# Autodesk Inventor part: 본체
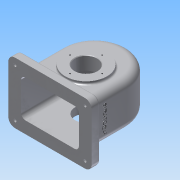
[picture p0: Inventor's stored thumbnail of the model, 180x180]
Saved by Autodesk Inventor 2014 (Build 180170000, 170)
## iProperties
Created: 2016-10
Part Number: 본체
Material: 알루미늄 6061
Document SubType Name: Modeling
Designer: net
Density: 2.71 g/cm^3
Appearance: 알루미늄 - 평지
Author: net
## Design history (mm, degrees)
sketch "스케치1"
  geometry: L1 (-63, 55)-(63, 55); L2 (75, 43)-(75, -43); L3 (63, -55)-(-63, -55); L4 (-75, -43)-(-75, 43); L5 (-75, 55)-(75, -55); L6 (75, 55)-(-75, -55); A1 r 12 centre (63, -43) between (63, -55) and (75, -43); A2 r 12 centre (-63, -43) between (-75, -43) and (-63, -55); A3 r 12 centre (-63, 43) between (-63, 55) and (-75, 43); A4 r 12 centre (63, 43) between (75, 43) and (63, 55); 1 further point
  constraints: 12 end point, 8 point on circle, 8 point on line, 8 tangent, 4 centre point, 3 equal radius, 2 midpoint, 2 parallel, 1 horizontal, 1 perpendicular
  dimensions: "d0" = 150 distance of L5.end L6.end; "d1" = 110 distance of L6.start L5.end; "d2" = 12 radius of A1
extrude "돌출1" new body sketch "스케치1" distance "d3" = 15; taper "d4" = 0 deg
fillet "모깎기1" dims "d5" = 3
sketch "스케치2"
  geometry: L1 (-58, 0)-(58, 0); L2 (58, 0)-(58, 80); L3 (58, 80)-(-58, 80); L4 (-58, 80)-(-58, 0); 2 further points
  constraints: 8 end point, 2 coincident, 2 parallel, 1 horizontal, 1 midpoint, 1 perpendicular
  dimensions: "d6" = 116 distance of L3.end L2.end; "d7" = 80 distance of L2.end L1.end
extrude "돌출2" join sketch "스케치2" stored distance "d8" = 77; taper "d9" = 0 deg
sketch "스케치3"
  geometry: L1 (-58, 80)-(58, 80) reference; 2 further points
  constraints: 1 horizontal alignment, 1 midpoint, 2 other
extrude "돌출3" join sketch "스케치3" stored distance "d10" = 77; taper "d11" = 0 deg
sketch "스케치4"
  geometry: L1 (-58, 15)-(-58, 80) reference; L2 (58, 80)-(58, 15) reference; L3 (-63, 0)-(63, 0) reference; L4 (-52, 0)-(-52, 80); L5 (52, 80)-(52, 0); L6 (52, 0)-(-52, 0); A1 r 58 centre (0, 80) between (58, 80) and (-58, 80) reference; A2 r 52 centre (0, 80) between (52, 80) and (-52, 80); 1 further point
  constraints: 6 end point, 2 parallel, 2 point on circle, 2 point on line, 2 tangent, 1 centre point, 1 collinear
  dimensions: "d12" = 6 radial gap between concentric circles of A2 A1
extrude "돌출4" cut sketch "스케치4" stored distance "d13" = 67; taper "d14" = 0 deg
sketch "스케치5"
  geometry: L1 (63, 0)-(-63, 0) reference; C1 r 31 at (0, 65); 2 further points
  constraints: 1 centre point, 1 midpoint, 1 vertical alignment
  dimensions: "d15" = 62 diameter of C1; "d16" = 65 distance from line of L1 C1.centre
extrude "돌출5" join sketch "스케치5" distance "d17" = 10; taper "d18" = 0 deg
sketch "스케치6"
  geometry: C1 r 31 at (0, 0) reference; C2 r 20 at (0, 0); 1 further point
  constraints: 1 centre point, 1 coincident
  dimensions: "d19" = 40 diameter of C2
extrude "돌출6" cut sketch "스케치6" distance "d20" = 15; taper "d21" = 0 deg
sketch "스케치7"
  geometry: L1 (63, 0)-(-63, 0) reference; C1 r 37.5 at (0, 65); 2 further points
  constraints: 1 centre point, 1 midpoint, 1 vertical alignment
  dimensions: "d22" = 75 diameter of C1; "d23" = 65 distance from line of L1 C1.centre
extrude "돌출7" join sketch "스케치7" distance "d24" = 5; taper "d25" = 0 deg
sketch "스케치8"
  geometry: C1 r 37.5 at (0, 0) reference; C2 r 20 at (0, 0); 1 further point
  constraints: 1 centre point, 1 coincident
  dimensions: "d26" = 40 diameter of C2
extrude "돌출8" cut sketch "스케치8" distance "d27" = 24; taper "d28" = 0 deg
sketch "스케치9"
  geometry: C1 r 20 at (0, 65) reference; C2 r 28 at (0, 65); 1 further point
  constraints: 1 centre point, 1 coincident
  dimensions: "d29" = 56 diameter of C2
extrude "돌출9" join sketch "스케치9" distance "d30" = 14; taper "d31" = 0 deg
feature "면 기울기1" dims angle "d32" = 40 deg
sketch "스케치11"
  geometry: A1 r 9 centre (63, 43) between (72, 43) and (63, 52) reference; A2 r 9 centre (-63, 43) between (-63, 52) and (-72, 43) reference; A3 r 9 centre (-63, -43) between (-72, -43) and (-63, -52) reference; A4 r 9 centre (63, -43) between (63, -52) and (72, -43) reference; 5 further points
  constraints: 4 coincident
hole "구멍1" sketch "스케치11" at (-63, 43), (63, 43), (63, -43), (-63, -43) diameter "d33" = 5; stored, may be unused: countersink angle "d37" = 90 deg, drill point angle "d39" = 0 deg; dims "d34" = 6, "d35" = 12, "d36" = 5, "d38" = 20
fillet "모깎기2" dims "d40" = 13, "d41" = 8
node "작업 평면1"
sketch "스케치12"
  geometry: C1 r 6 at (0, 0); 1 further point
  constraints: 1 centre point, 1 coincident
  dimensions: "d43" = 12 diameter of C1
extrude "돌출10" join sketch "스케치12" stored distance "d44" = 14; taper "d45" = 0 deg
feature "면 기울기2" dims angle "d46" = 10 deg
sketch "스케치14"
  geometry: C1 r 6 at (0, 0) reference; 1 further point
  constraints: 1 coincident
hole "구멍2" sketch "스케치14" at (0, 0) diameter "d47" = 4.459; stored, may be unused: countersink angle "d51" = 90 deg, drill point angle "d53" = 118 deg; dims "d48" = 30, "d49" = 12, "d50" = 5, "d52" = 30
sketch "스케치15"
  geometry: C1 r 20 at (0, 0) reference; 5 further points
  constraints: 1 horizontal alignment, 5 other
  dimensions: "d54" = 29 distance of point (29, 0) C1.centre; "d57" = 360 deg dimension on C1.centre point (29, 0) (derived)
hole "구멍3" sketch "스케치15" at (29, 0), (0, 29), (-29, 0), (0, -29) diameter "d59" = 2.459; stored, may be unused: countersink angle "d63" = 90 deg, drill point angle "d65" = 118 deg; dims "d60" = 6, "d61" = 4, "d62" = 2, "d64" = 8
sketch "스케치16"
  geometry: C1 r 20 at (0, 0) reference; 5 further points
  constraints: 1 horizontal alignment, 5 other
  dimensions: "d66" = 26 distance of point (26, 0) C1.centre; "d69" = 360 deg dimension on C1.centre point (26, 0) (derived)
hole "구멍4" sketch "스케치16" at (26, 0), (0, 26), (-26, 0), (0, -26) diameter "d71" = 2.459; stored, may be unused: countersink angle "d75" = 90 deg, drill point angle "d77" = 118 deg; dims "d72" = 6, "d73" = 4, "d74" = 2, "d76" = 8
chamfer "모따기1" distance "d78" = 1; stored, may be unused: second distance "d79" = 2, angle "d80" = 45 deg
node "작업 평면2"
sketch "스케치17"
  geometry: L1 (17.5, -15)-(-68.5, -15) reference; 3 further points
  constraints: 1 midpoint, 1 vertical alignment, 1 other
  dimensions: "d82" = 40 distance from line of L1 point (-25.5, 25)
feature "엠보싱1" sketch "스케치17" dims "d0" = 150, "d1" = 110, "d2" = 12, "d83" = 0.5, "d84" = 0
fillet "모깎기3" dims "d85" = 3
node "솔리드1"
other parameters: "d42" = 144, "d81" = 5
